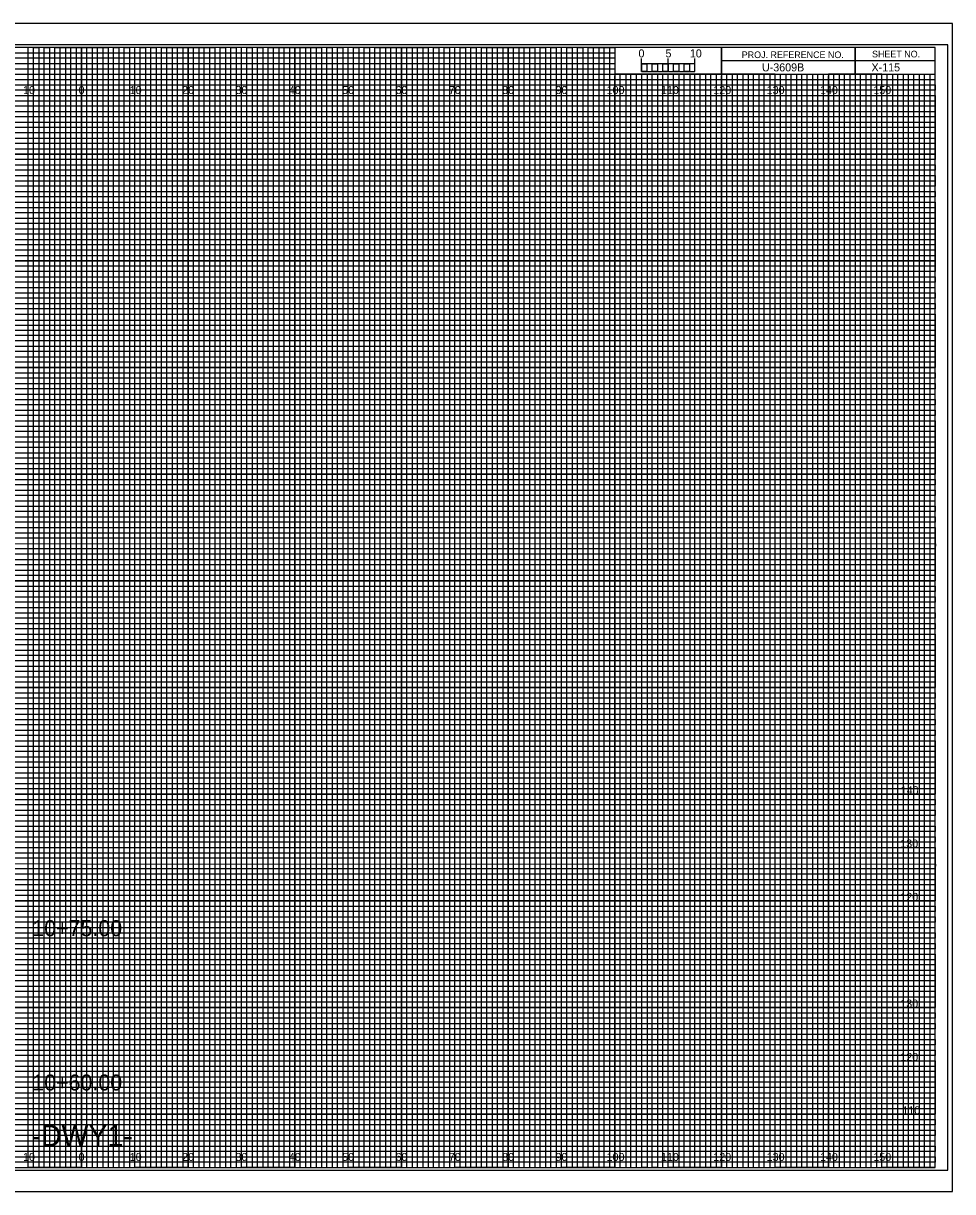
# Model space of a CAD drawing. Extents: x -13 to 323, y -5 to 215.
# Drawn here: x 149.1 to 323.3, y -4.5 to 214.5 of the extents above; entities that cross this region are included whole.
import ezdxf

# ---------------------------------------------------------------- set-up
doc = ezdxf.new("R2010")
doc.units = 0
for name, color, linetype in [('Exist Cross Section Cell', 7, 'Continuous'), ('Prop XS Alignment Label', 7, 'Continuous'), ('Prop XS Bar Scale Labels', 7, 'Continuous'), ('Prop XS Elevation Labels', 7, 'Continuous'), ('Prop XS Project Number', 7, 'Continuous'), ('Prop XS Sheet Number', 7, 'Continuous'), ('Prop XS Station Labels', 7, 'Continuous'), ('Sheet Cross Section CELL', 7, 'Continuous'), ('Sheet Cross Section Grid Major CELL', 7, 'Continuous'), ('Sheet Cross Section Grid Middle CELL', 7, 'Continuous'), ('Sheet Cross Section Grid Minor 1 CELL', 7, 'Continuous'), ('Sheet Cross Section Grid Minor 2 CELL', 7, 'Continuous'), ('Sheet Cross Section Scale CELL', 7, 'Continuous'), ('Sheet Cutting Line CELL', 7, 'Continuous'), ('Sheet DOT Grid CELL', 7, 'Continuous'), ('Sheet Plot Border Inside CELL', 7, 'Continuous'), ('Sheet Plot Border Outside CELL', 7, 'Continuous')]:
    doc.layers.add(name, color=color, linetype=linetype)

msp = doc.modelspace()

# ---------------------------------------------------------------- linework, layer by layer
at = {"layer": 'Sheet Cross Section CELL'}
for p, q in [((305, 210), (305, 205)), ((305, 205), (305, 210)), ((280, 207.5), (280, 205)), ((320, 207.49), (280, 207.49)), ((280, 205), (320, 205))]:
    msp.add_line(p, q, dxfattribs=at)
for points in [[(320, 210), (0, 210), (0, 0), (320, 0)], [(280, 210), (260, 210), (260, 205.03), (280, 205.03)], [(320, 210), (280, 210), (280, 205), (320, 205)]]:
    msp.add_lwpolyline(points, close=True, dxfattribs=at)
at = {"layer": 'Sheet Cross Section Grid Major CELL'}
for p, q in [((150, 210), (140, 210)), ((150, 0), (150, 210)), ((170, 210), (160, 210)), ((160, 210), (160, 0)), ((170, 0), (170, 210)), ((190, 210), (180, 210)), ((180, 210), (180, 0)), ((190, 0), (190, 210)), ((210, 210), (200, 210)), ((200, 210), (200, 0)), ((210, 0), (210, 210)), ((230, 210), (220, 210)), ((220, 210), (220, 0)), ((230, 0), (230, 210)), ((250, 210), (240, 210)), ((240, 210), (240, 0)), ((250, 0), (250, 210)), ((260, 210), (260, 0)), ((270, 0), (270, 205)), ((290, 205), (280, 205)), ((280, 205), (280, 0)), ((290, 0), (290, 205)), ((310, 205), (300, 205)), ((300, 205), (300, 0)), ((310, 0), (310, 205)), ((160, 0), (150, 0)), ((180, 0), (170, 0)), ((200, 0), (190, 0)), ((220, 0), (210, 0)), ((240, 0), (230, 0)), ((260, 0), (250, 0)), ((280, 0), (270, 0)), ((300, 0), (290, 0)), ((320, 0), (310, 0)), ((320, 0), (320, 0))]:
    msp.add_line(p, q, dxfattribs=at)
for points in [[(0, 200), (320, 200), (320, 190), (0, 190)], [(0, 180), (320, 180), (320, 170), (0, 170)], [(0, 160), (320, 160), (320, 150), (0, 150)], [(0, 140), (320, 140), (320, 130), (0, 130)], [(0, 120), (320, 120), (320, 110), (0, 110)], [(0, 100), (320, 100), (320, 90), (0, 90)], [(0, 80), (320, 80), (320, 70), (0, 70)], [(0, 60), (320, 60), (320, 50), (0, 50)], [(0, 40), (320, 40), (320, 30), (0, 30)], [(0, 20), (320, 20), (320, 10), (0, 10)]]:
    msp.add_lwpolyline(points, dxfattribs=at)
at = {"layer": 'Sheet Cross Section Grid Middle CELL'}
for points in [[(145, 0), (155, 0), (155, 210), (165, 210), (165, 0), (175, 0), (175, 210), (185, 210), (185, 0), (195, 0), (195, 210), (205, 210), (205, 0), (215, 0), (215, 210), (225, 210), (225, 0), (235, 0), (235, 210), (245, 210), (245, 0), (255, 0), (255, 210), (259.93, 210), (260, 210), (260, 205), (264.99, 205), (264.99, 0), (275, 0), (275, 205), (285, 205), (285, 0), (295, 0), (295, 205), (305, 205), (305, 0), (315, 0), (315, 205)], [(0, 205), (275, 205)], [(0, 185), (320, 185), (320, 195), (0, 195)], [(0, 165), (320, 165), (320, 175), (0, 175)], [(0, 145), (320, 145), (320, 155), (0, 155)], [(0, 125), (320, 125), (320, 135), (0, 135)], [(0, 105), (320, 105), (320, 115), (0, 115)], [(0, 85), (320, 85), (320, 95), (0, 95)], [(0, 65), (320, 65), (320, 75), (0, 75)], [(0, 45), (320, 45), (320, 55), (0, 55)], [(0, 25), (320, 25), (320, 35), (0, 35)], [(0, 5), (320, 5), (320, 15), (0, 15)]]:
    msp.add_lwpolyline(points, dxfattribs=at)
at = {"layer": 'Sheet Cross Section Grid Minor 1 CELL'}
for p, q in [((0, 209), (260, 209)), ((260, 209), (260, 207.98)), ((260, 207.98), (0, 207.98)), ((0, 207), (260, 207)), ((260, 205.89), (0, 205.89)), ((260, 207), (260, 205.89)), ((0, 204), (320, 204))]:
    msp.add_line(p, q, dxfattribs=at)
for points in [[(0, 203), (270, 203), (320, 203), (320, 202), (0, 202)], [(0, 201), (320, 201), (320, 199), (0, 199)], [(0, 198), (320, 198), (320, 197), (0, 196.98)], [(0, 196), (320, 196), (320, 194), (0, 194)], [(0, 193), (320, 193), (320, 192), (0, 192)], [(0, 191), (320, 191), (320, 189), (0, 189)], [(0, 188), (320, 188), (320, 187), (0, 187)], [(0, 186), (320, 186), (320, 184), (0, 184)], [(0, 183), (320, 183), (320, 182), (0, 182)], [(0, 181), (320, 181), (320, 179), (0, 179)], [(0, 178), (320, 178), (320, 177), (0, 177)], [(0, 176), (320, 176), (320, 173.95), (320, 173), (320, 172), (0, 172)], [(0, 174), (320, 174), (320, 173), (0, 173)], [(0, 171), (320, 171), (320, 169), (0, 169.03)], [(0, 169.03), (320, 169), (320, 168), (0, 168)], [(0, 167), (320, 167), (320, 166), (0, 166)], [(0, 164), (320, 164), (320, 163), (0, 163)], [(0, 162), (320, 162), (320, 161), (0, 161)], [(-0.07, 158.89), (320, 158.89), (320, 157.88), (-0.07, 157.88)], [(0, 157), (320, 157), (320, 156), (0, 156)], [(0, 154), (320, 154), (320, 153), (0, 153)], [(0, 152), (320, 152), (320, 151), (0, 151)], [(0, 149), (320, 149), (320, 148), (0, 148)], [(0, 147), (320, 147), (320, 146), (0, 146)], [(0, 144), (320, 144), (320, 143), (0, 143)], [(0, 142), (320, 142), (320, 141), (0, 141)], [(0, 139), (320, 139), (319.99, 137.98), (0, 138)], [(0, 137), (320, 137), (320, 136), (0, 136)], [(0, 134), (320, 134), (320, 133), (0, 133)], [(0, 132), (320, 132), (320, 131), (0, 131)], [(0, 129), (320, 129), (320, 128), (0, 128)], [(0, 127), (320, 127), (320, 126), (0, 126)], [(0, 124), (320, 124), (320, 123), (0, 123)], [(0, 122), (320, 122), (320, 121), (0, 121)], [(0, 119), (320, 119), (320, 118), (0, 118)], [(0, 116.99), (320.07, 116.91), (320, 116), (0, 116)], [(0, 114), (320, 114), (320, 113), (0, 113)], [(0, 112), (320, 112), (320, 111), (0, 111)], [(0, 109), (320, 109), (320, 108), (0, 108)], [(0, 107), (320, 107), (320, 106), (0, 106)], [(0, 104), (320, 104), (320, 103), (0, 103)], [(0, 102), (320, 102), (320, 101), (0, 101)], [(0, 99), (320, 99), (320, 98), (0, 98)], [(0, 97), (320, 97), (320, 96), (0, 96)], [(0, 94), (320, 94), (320, 93), (0, 93)], [(0, 92), (320, 92), (320, 91), (0, 91)], [(0, 89), (320, 89), (320, 88), (0, 88)], [(0, 87), (320, 87), (320, 86), (0, 86)], [(0, 84), (320, 84), (320, 83), (0, 83)], [(0, 82), (320, 82), (320, 81), (0, 81)], [(0, 79), (320, 79), (319.99, 77.98), (0, 78)], [(0, 77), (320, 77), (320, 76), (0, 76)], [(0, 74), (320, 74), (320, 73), (0, 73)], [(0, 72), (320, 72), (320, 71), (0, 71)], [(0, 69), (320, 69), (320, 68), (0, 68)], [(0, 67), (320, 67), (320, 66), (0, 66)], [(0, 64), (320, 64), (320, 63), (0, 63)], [(0, 62), (320, 62), (320, 61), (0, 61)], [(0, 59), (320, 59), (320, 58), (0, 58)], [(0, 56.99), (320.07, 56.91), (320, 56), (0, 56)], [(0, 54), (320, 54), (320, 53), (0, 53)], [(0, 52), (320, 52), (320, 51), (0, 51)], [(0, 49), (320, 49), (320, 48), (0, 48)], [(0, 47), (320, 47), (320, 46), (0, 46)], [(0, 44), (320, 44), (320, 43), (0, 43)], [(0, 42), (320, 42), (320, 41), (0, 41)], [(0, 39), (320, 39), (320, 38), (0, 38)], [(0, 37), (320, 37), (320, 36), (0, 36)], [(0, 34), (320, 34), (320, 33), (0, 33)], [(0, 32), (320, 32), (320, 31), (0, 31)], [(0, 29), (320, 29), (320, 28), (0, 28)], [(0, 27), (320, 27), (320, 26), (0, 26)], [(0, 24), (320, 24), (320, 23), (0, 23)], [(0, 22), (320, 22), (320, 21), (0, 21)], [(0, 19), (320, 19), (320, 18), (0, 18)], [(0, 17), (320, 17), (320, 16), (0, 16)], [(0, 14), (320, 14), (320, 13), (0, 13)], [(0, 12), (320, 12), (320, 11), (0, 11)], [(0, 9), (320, 9), (320, 8), (0, 8)], [(0, 7), (320, 7), (320, 6), (0, 6)], [(0, 4), (320, 4), (320, 3), (0, 3)], [(0, 2), (320, 2), (320, 1), (0, 1)]]:
    msp.add_lwpolyline(points, dxfattribs=at)
at = {"layer": 'Sheet Cross Section Grid Minor 2 CELL'}
for p, q in [((267, 205), (266.01, 205)), ((266.01, 205), (266.01, 0)), ((267, 0), (267, 205)), ((269, 205), (268, 205)), ((268, 205), (268, 0)), ((269, 0), (269, 205)), ((266.01, 0), (265, 0)), ((268, 0), (267, 0))]:
    msp.add_line(p, q, dxfattribs=at)
for points in [[(150, 0), (151, 0), (151, 210), (152, 210), (152, 0)], [(152, 0), (153, 0), (153, 210), (154, 210), (154, 0)], [(155, 0), (156, 0), (156, 210), (157, 210), (157, 0)], [(157, 0), (158, 0), (158, 210), (159, 210), (159, 0)], [(160, 0), (161, 0), (161, 210), (162, 210), (162, 0)], [(162, 0), (163, 0), (163, 210), (164, 210), (164, 0)], [(165, 0), (166, 0), (166, 210), (167, 210), (167, 0)], [(167, 0), (168, 0), (168, 210), (169, 210), (169, 0)], [(170, 0), (171, 0), (171, 210), (172, 210), (172, 0)], [(172, 0), (173, 0), (173, 210), (174, 210), (174, 0)], [(175, 0), (176, 0), (176, 210), (177, 210), (177, 0)], [(177, 0), (178, 0), (178, 210), (179, 210), (179, 0)], [(180, 0), (181, 0), (181, 210), (182, 210), (182, 0)], [(182, 0), (183, 0), (183, 210), (184, 210), (184, 0)], [(185, 0), (186, 0), (186, 210), (187, 210), (187, 0)], [(187, 0), (188, 0), (188, 210), (189, 210), (189, 0)], [(190, 0), (191, 0), (191, 210), (192, 210), (192, 0)], [(192, 0), (193, 0), (193, 210), (194, 210), (194, 0)], [(195, 0), (196, 0), (196, 210), (197, 210), (197, 0)], [(197, 0), (198, 0), (198, 210), (199, 210), (199, 0)], [(200, 0), (201, 0), (201, 210), (202, 210), (202, 0)], [(202, 0), (203, 0), (203, 210), (204, 210), (204, 0)], [(205, 0), (206, 0), (206, 210), (207, 210), (207, 0)], [(207, 0), (208, 0), (208, 210), (209, 210), (209, 0)], [(210, 0), (211, 0), (211, 210), (212, 210), (212, 0)], [(212, 0), (213, 0), (213, 210), (214, 210), (214, 0)], [(215, 0), (216, 0), (216, 210), (217, 210), (217, 0)], [(217, 0), (218, 0), (218, 210), (219, 210), (219, 0)], [(220, 0), (221, 0), (221, 210), (222, 210), (222, 0)], [(222, 0), (223, 0), (223, 210), (224, 210), (224, 0)], [(225, 0), (226, 0), (226, 210), (227, 210), (227, 0)], [(227, 0), (228, 0), (228, 210), (229, 210), (229, 0)], [(230, 0), (231, 0), (231, 210), (232, 210), (232, 0)], [(232, 0), (233, 0), (233, 210), (234, 210), (234, 0)], [(235, 0), (236, 0), (236, 210), (237, 210), (237, 0)], [(237, 0), (238, 0), (238, 210), (239, 210), (239, 0)], [(240, 0), (241, 0), (241, 210), (242, 210), (242, 0)], [(242, 0), (243, 0), (243, 210), (244, 210), (244, 0)], [(245, 0), (246, 0), (246, 210), (247, 210), (247, 0)], [(247, 0), (248, 0), (248, 210), (249, 210), (249, 0)], [(250, 0), (251, 0), (251, 210), (252, 210), (252, 0)], [(252, 0), (253, 0), (253, 210), (254, 210), (254, 0)], [(255, 0), (256, 0), (256, 210), (257, 210), (257, 0)], [(257, 0), (258, 0), (258, 210), (259, 210), (259, 0)], [(260, 0), (261, 0), (261, 205), (262.02, 205), (262.02, 0)], [(262, 0), (263, 0), (263, 205), (263.99, 205), (263.99, 0)], [(270, 0), (270.98, 0), (270.98, 205), (272, 205), (272, 0)], [(272, 0), (273, 0), (273, 205), (274.05, 205), (274.05, 0)], [(275, 0), (276, 0), (276, 205), (277, 205), (277, 0)], [(277, 0), (278, 0), (278, 205), (279, 205), (279, 0)], [(280, 0), (281, 0), (281, 205), (282, 205), (282, 0)], [(282, 0), (283, 0), (283, 205), (284, 205), (284, 0)], [(285, 0), (286, 0), (286, 205), (287, 205), (287, 0)], [(287, 0), (288, 0), (288, 205), (289, 205), (289, 0)], [(290, 0), (291, 0), (291, 205), (292, 205), (292, 0)], [(292, 0), (293, 0), (293, 205), (294, 205), (294, 0)], [(295, 0), (296, 0), (296, 205), (297, 205), (297, 0)], [(297, 0), (298, 0), (298, 205), (299, 205), (299, 0)], [(300, 0), (301, 0), (301, 205), (302, 205), (302, 0)], [(302, 0), (303, 0), (303, 205), (304, 205), (304, 0)], [(305, 0), (306, 0), (306, 205), (307, 205), (307, 0)], [(307, 0), (308, 0), (308, 205), (309, 205), (309, 0)], [(310, 0), (311, 0), (311, 205), (312, 205), (312, 0)], [(312, 0), (313, 0), (313, 205), (314, 205), (314, 0)], [(315, 0), (316, 0), (316, 205), (317, 205), (317, 0)], [(317, 0), (318, 0), (318, 205), (319, 205), (319, 0)]]:
    msp.add_lwpolyline(points, dxfattribs=at)
at = {"layer": 'Sheet Cross Section Scale CELL'}
for p, q in [((265, 205.49), (265, 207.9)), ((265, 206.9), (265, 207.9)), ((270, 205.49), (270, 207.9)), ((275, 205.49), (275, 207.9)), ((275, 206.9), (275, 207.9))]:
    msp.add_line(p, q, dxfattribs=at)
for points in [[(275, 206.9), (265, 206.9), (265, 205.49), (275, 205.49)], [(265, 206.9), (266, 206.9), (266, 205.49), (265, 205.49)], [(267, 206.9), (268, 206.9), (268, 205.49), (267, 205.49)], [(269, 206.9), (270, 206.9), (270, 205.49), (269, 205.49)], [(271, 206.9), (272, 206.9), (272, 205.49), (271, 205.49)], [(273, 206.9), (274, 206.9), (274, 205.49), (273, 205.49)]]:
    msp.add_lwpolyline(points, close=True, dxfattribs=at)
at = {"layer": 'Sheet Cutting Line CELL'}
for p, q in [((323.3, 214.5), (-13.4, 214.5)), ((-13.4, -4.5), (323.3, -4.5))]:
    msp.add_line(p, q, dxfattribs=at)
at = {"layer": 'Sheet DOT Grid CELL'}
for p, q in [((150, 0), (150, 210)), ((160, 0), (160, 210)), ((170, 0), (170, 210)), ((180, 0), (180, 210)), ((190, 0), (190, 210)), ((200, 0), (200, 210)), ((210, 0), (210, 210)), ((220, 0), (220, 210)), ((230, 0), (230, 210)), ((240, 0), (240, 210)), ((250, 0), (250, 210)), ((260, 0), (260, 204.69)), ((270, 0), (270, 204.69)), ((280, 0), (280, 204.69)), ((290, 0), (290, 204.69)), ((300, 0), (300, 204.69)), ((310, 0), (310, 204.69)), ((0, 200), (320, 200)), ((0, 190), (320, 190)), ((0, 180), (320, 180)), ((0, 170), (320, 170)), ((0, 160), (320, 160)), ((0, 150), (320, 150)), ((0, 140), (320, 140)), ((0, 130), (320, 130)), ((0, 120), (320, 120)), ((0, 110), (320, 110)), ((0, 100), (320, 100)), ((0, 90), (320, 90)), ((0, 80), (320, 80)), ((0, 70), (320, 70)), ((0, 60), (320, 60)), ((0, 50), (320, 50)), ((0, 40), (320, 40)), ((0, 30), (320, 30)), ((0, 20), (320, 20)), ((0, 10), (320, 10))]:
    msp.add_line(p, q, dxfattribs=at)
at = {"layer": 'Sheet Plot Border Inside CELL'}
msp.add_lwpolyline([(-10.8, -0.5), (322.4, -0.5), (322.4, 210.5), (-10.8, 210.5)], close=True, dxfattribs=at)
at = {"layer": 'Sheet Plot Border Outside CELL'}
msp.add_lwpolyline([(-13.4, -4.5), (323.3, -4.5), (323.3, 214.5), (-13.4, 214.5)], close=True, dxfattribs=at)

# ---------------------------------------------------------------- texts
at = {"layer": 'Exist Cross Section Cell'}
for s, p in [('10', (149.04, 201.25)), ('0', (159.45, 201.25)), ('0', (159.45, 201.25)), ('10', (169.04, 201.25)), ('20', (178.86, 201.25)), ('30', (188.86, 201.25)), ('40', (198.86, 201.25)), ('50', (208.86, 201.25)), ('60', (218.86, 201.25)), ('70', (228.86, 201.25)), ('80', (238.86, 201.25)), ('90', (248.86, 201.25)), ('100', (258.44, 201.25)), ('110', (268.62, 201.25)), ('120', (278.44, 201.25)), ('130', (288.44, 201.25)), ('140', (298.44, 201.25)), ('150', (308.44, 201.25)), ('10', (149.04, 1.25)), ('0', (159.45, 1.25)), ('0', (159.45, 1.25)), ('10', (169.04, 1.25)), ('20', (178.86, 1.25)), ('30', (188.86, 1.25)), ('40', (198.86, 1.25)), ('50', (208.86, 1.25)), ('60', (218.86, 1.25)), ('70', (228.86, 1.25)), ('80', (238.86, 1.25)), ('90', (248.86, 1.25)), ('100', (258.44, 1.25)), ('110', (268.62, 1.25)), ('120', (278.44, 1.25)), ('130', (288.44, 1.25)), ('140', (298.44, 1.25)), ('150', (308.44, 1.25))]:
    msp.add_text(s, height=1.5, dxfattribs=at).set_placement(p)
at = {"layer": 'Prop XS Alignment Label'}
msp.add_text('-DWY1-', height=4, dxfattribs=at).set_placement((150.6, 4))
at = {"layer": 'Prop XS Bar Scale Labels'}
for s, p in [('5', (269.47, 208.12)), ('10', (274.04, 208.12))]:
    msp.add_text(s, height=1.5, dxfattribs=at).set_placement(p)
at = {"layer": 'Prop XS Elevation Labels'}
for s, p in [('140', (313.57, 70)), ('130', (313.49, 60)), ('120', (313.5, 50)), ('130', (313.49, 30)), ('120', (313.5, 20)), ('110', (313.88, 10))]:
    msp.add_text(s, height=1.5, dxfattribs=at).set_placement(p)
at = {"layer": 'Prop XS Project Number'}
msp.add_text('U-3609B', height=1.5, dxfattribs=at).set_placement((287.56, 205.5))
at = {"layer": 'Prop XS Sheet Number'}
msp.add_text('X-115', height=1.5, dxfattribs=at).set_placement((308.09, 205.5))
at = {"layer": 'Prop XS Station Labels'}
for s, p in [('10+75.00', (150.77, 43.39)), ('10+60.00', (150.77, 14.46))]:
    msp.add_text(s, height=3, dxfattribs=at).set_placement(p)
at = {"layer": 'Sheet Cross Section CELL'}
for s, p in [('PROJ. REFERENCE NO.', (283.77, 207.99)), ('SHEET NO.', (308.19, 208.12))]:
    msp.add_text(s, height=1.25, dxfattribs=at).set_placement(p)
at = {"layer": 'Sheet Cross Section Scale CELL'}
msp.add_text('0', height=1.5, dxfattribs=at).set_placement((264.41, 208.12))

doc.saveas('drawing.dxf')
